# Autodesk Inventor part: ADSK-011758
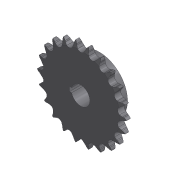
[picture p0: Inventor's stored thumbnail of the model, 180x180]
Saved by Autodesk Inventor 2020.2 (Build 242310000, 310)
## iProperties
Created: 1999-12
Part Number: ADSK-011758
Material: Acier (alliage faible hypertrempé)
Description: SPROCKET,B,50B22,1.00B,NO KEY
Document SubType Name: Modeling
Designer: gpurviance
Density: 7.84 g/cm^3
Appearance: Metal-Steel(Polish)
Mass: 1115.15 g
Surface Area: 279.325 cm^2
Volume: 142.239 cm^3
Control State: 0
Master: False
Checked Out: False
Shininess: 0.0
Length Units: 11269
Angle Units: 11279
Time Units: 11290
Mass Units: 11283
Length Display Precision: 3
Angle Display Precision: 2
Compacted: True
Material Desc: SPROCKET,B,40B
Material_number: A08xxxx
Dimensions: 120,4x25,4x121,6 mm
Mass: 1,115 kg
VLT_Material: Acier (alliage faible hypertrempé)
Density: 0.0
Volumn: 0.0
Area: 0.0
PropertySet Name: Model Information
Author: gpurviance
Revision Number: -
Title: SPROCKET,B,50B22,1.00B,NO KEY
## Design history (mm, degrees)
node "Solide1"
node "Corps solides"
node "Corps surfaciques"
node "Sprocket blank" dims "d1" = 8.7122 (= thk), "d2" = 0
node "Half of tooth shape" dims "d15" = 8.7122 (= thk), "d16" = 0
node "Sprocket centerline"
node "Hub" dims "d28" = 16.6878 (= hubthk), "d29" = 0
node "Bore extrusion" dims "d31" = 16.6878 (= hubthk), "d32" = 0 (computed from Taper)
node "Mirror of tooth half"
node "tooth array" dims "d17" = 220 (= N_1), "d19" = 2.85599 (computed from N_1)
node "Revolution2" dims "d46" = 90 deg
workplane "Arbeitsebene1"
sketch "Skizze8"
  geometry: L1 (-12.135, -3)-(-15, -3); L2 (-15, -3)-(-15, 3); L3 (-15, 3)-(-12.135, 3); A1 r 12.5 centre (0, 0) between (-12.135, -3) and (-12.135, 3) reference; 2 further points
  constraints: 6 end point, 2 perpendicular, 2 point on circle, 1 horizontal, 1 horizontal alignment, 1 midpoint
  dimensions: "d49" = 6 distance of L1.end L2.end; "d50" = 15 distance from line of point (0, 0) L2
extrude "Extrusion6" cut sketch "Skizze8" extent not by distance; stored distance "d51" = 0.004; taper "d52" = 0 deg
sketch "Sketch1"
  geometry: C1 r 50.694 at (0, 0)
  constraints: 1 centre point
  dimensions: "d0" = 50.69423 radius of C1 (computed from N_1, Pitch, Dr)
sketch "Sketch2" dims "d5" = 10.16 (= Dr)
  geometry: L1 (0, 60.833)-(0, 0); L2 (0, 0)-(17.139, 58.369); L3 (0, 0)-(8.657, 60.214); L4 (0, 55.774)-(-7.642, 55.774); L5 (4.018, 52.666)-(-6.429, 60.748); L6 (-6.429, 60.748)-(14.048, 52.361); L7 (-4.776, 61.473)-(17.347, 52.411); L8 (5.794, 55.742)-(6.285, 56.942); L9 (19.508, 67.172)-(14.02, 53.774); L10 (8.653, 60.181)-(7.215, 50.178); C1 r 50.694 at (0, 0) reference; C2 r 43.904 at (0, 0); A1 r 5.08 centre (0, 55.774) between (0, 50.694) and (4.018, 52.666); A2 r 13.208 centre (-6.429, 60.748) between (4.018, 52.666) and (5.794, 55.742); A3 r 8.359 centre (14.02, 53.774) between (8.653, 60.181) and (6.285, 56.942); A4 r 50.694 centre (0, 0) between (7.215, 50.178) and (0, 50.694)
  constraints: 20 end point, 8 point on circle, 5 centre point, 5 point on line, 4 coincident, 2 equal length, 2 tangent, 1 collinear, 1 horizontal, 1 midpoint, 1 parallel, 1 vertical, 1 vertical alignment, 3 other
  dimensions: "d7" = 8.18182 deg angle of L3 L1 (computed from N_1); "d8" = 8.18182 deg angle of L2 L3 (= d7); "d9" = 37.7273 deg angle of L5 L4 (computed from N_1); "d10" = 15.4545 deg angle of L6 L5 (computed from N_1); "d11" = 8.128 distance of L4.start L5.end (= 0.8 x Dr); "d12" = 1.29709 distance between parallel lines of L6 L7 (computed from Dr, N_1); "d13" = 60.83307 distance of L1.end L2.end (= 1.2 x d0); "d14" = 8.35862 distance between parallel lines of L9 L8 (computed from N_1, Dr); "d33" = 50.69423 radius of A4 (= d0); "d48" = 87.8078 diameter of C2
sketch "Sketch5"
  geometry: C1 r 50.694 at (0, 0) reference; C2 r 38.1 at (0, 0)
  constraints: 1 centre point, 1 coincident
  dimensions: "d27" = 76.2 diameter of C2 (= hubdia)
sketch "Sketch6"
  geometry: C1 r 38.1 at (0, 0) reference; C2 r 12.5 at (0, 0)
  constraints: 1 centre point, 1 coincident
  dimensions: "d30" = 25 diameter of C2 (= bore)
sketch "Sketch7"
  geometry: L1 (8.712, -10.106)-(8.712, 0) reference; L2 (0, 0)-(8.712, 0) reference; L3 (0, -10.106)-(0, 0) reference; L4 (1.984, 0)-(0, -7.938); L5 (6.728, 0)-(8.712, -7.938); L6 (0, 0)-(-4.356, 0); L7 (-4.356, 0)-(-4.356, -16.65); L8 (-4.356, -16.65)-(0, -16.65); L9 (0, -16.65)-(0, 0); L10 (-6.97, -60.8)-(11.326, -60.8) reference
  constraints: 12 end point, 4 point on line, 2 parallel, 1 horizontal, 1 perpendicular
  dimensions: "d40" = 1.98374 distance from line of L4.start L3 (= G); "d41" = 1.98374 distance from line of L5.start L1 (= G); "d42" = 7.9375 distance from line of L5.end L2 (= h); "d43" = 7.9375 distance from line of L4.end L2 (= h); "d44" = 8.7122 distance from line of L8 L5.end (= thk); "d45" = 4.3561 distance between parallel lines of L3 L7 (= 0.5 x thk)
other parameters: "Pitch" = 15.875 [user parameter; used in 1 equation term], "Dr" = 10.16 [user parameter; used in 5 equation terms], "thk" = 8.7122 [user parameter; used in 5 equation terms], "h" = 7.9375 [user parameter; used in 2 equation terms], "G" = 1.98374 [user parameter; used in 2 equation terms], "hubdia" = 76.2 [user parameter; used in 1 equation term], "hubthk" = 16.6878 (computed from thk) [user parameter; used in 2 equation terms], "bore" = 25 [user parameter; used in 1 equation term], "Taper" = 0 [user parameter; used in 1 equation term]
